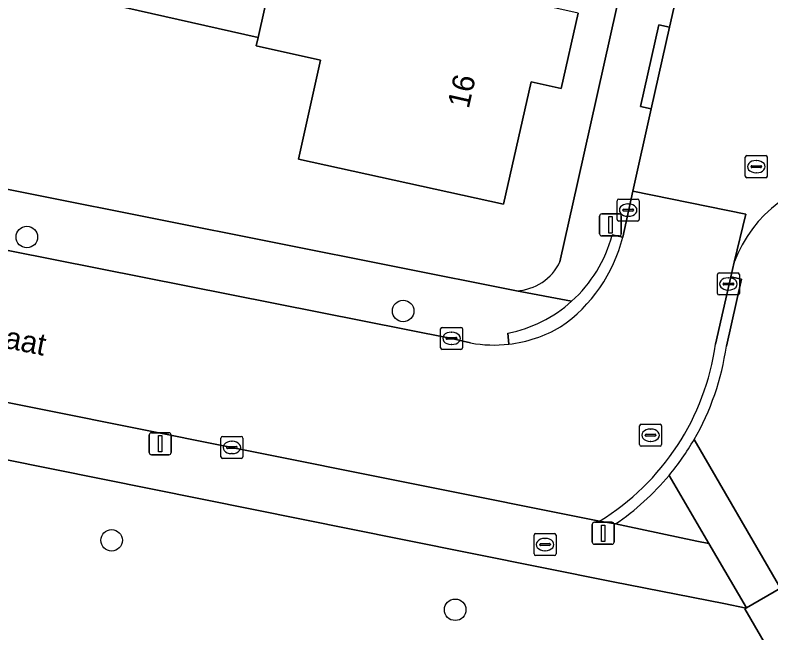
# Model space of a CAD drawing. Extents: x 161771 to 163125, y 382475 to 383179.
# Drawn here: x 162596.63 to 162630.99, y 382576.02 to 382604.09 of the extents above; entities that cross this region are included whole.
import ezdxf

# ---------------------------------------------------------------- set-up
doc = ezdxf.new("R2010")
doc.units = 0
for name, color, linetype in [('IMGEO_Boom', 7, 'Continuous'), ('IMGEO_Brandkraan', 7, 'Continuous'), ('IMGEO_Erf', 7, 'Continuous'), ('IMGEO_Groenvoorziening', 7, 'Continuous'), ('IMGEO_Kolk', 7, 'Continuous'), ('IMGEO_Lichtmast', 7, 'Continuous'), ('IMGEO_Openbare_ruimte_label', 7, 'Continuous'), ('IMGEO_Pand', 7, 'Continuous'), ('IMGEO_Pand_nummerreeks', 7, 'Continuous'), ('IMGEO_Rijbaan_lokaal_open', 7, 'Continuous'), ('IMGEO_Rioolput', 7, 'Continuous'), ('IMGEO_Voetpad_gesloten', 7, 'Continuous'), ('IMGEO_Voetpad_open', 7, 'Continuous')]:
    doc.layers.add(name, color=color, linetype=linetype)

msp = doc.modelspace()

# ---------------------------------------------------------------- linework, layer by layer
at = {"layer": 'IMGEO_Boom'}
for centre in [(162597.163, 382594.003), (162614.272, 382590.645), (162601.016, 382580.221), (162616.637, 382577.065)]:
    msp.add_circle(centre, 0.489, dxfattribs=at)
at = {"layer": 'IMGEO_Brandkraan'}
for p, q in [((162620.221, 382579.603), (162620.221, 382580.455)), ((162620.296, 382580.529), (162621.148, 382580.529)), ((162620.709, 382580.309), (162620.734, 382580.309)), ((162621.222, 382580.455), (162621.222, 382579.603)), ((162620.48, 382580.023), (162620.48, 382580.035)), ((162620.918, 382579.986), (162620.52, 382579.986)), ((162620.523, 382580.072), (162620.921, 382580.072)), ((162620.964, 382580.035), (162620.964, 382580.023)), ((162620.732, 382579.749), (162620.707, 382579.749)), ((162621.148, 382579.529), (162620.296, 382579.529))]:
    msp.add_line(p, q, dxfattribs=at)
for points in [[(162620.221, 382579.603), (162620.221, 382580.455)], [(162620.296, 382580.529), (162621.148, 382580.529)], [(162621.222, 382580.455), (162621.222, 382579.603)], [(162621.148, 382579.529), (162620.296, 382579.529)]]:
    msp.add_lwpolyline(points, dxfattribs=at)
for centre, radius, start, end in [((162620.298, 382580.453), 0.0765, 91.552, 178.448), ((162620.298, 382580.453), 0.0765, 91.552, 178.448), ((162621.146, 382580.453), 0.0765, 1.552, 88.448), ((162621.146, 382580.453), 0.0765, 1.552, 88.448), ((162620.52, 382580.032), 0.0403, 85.8775, 175.7526), ((162620.517, 382580.022), 0.0366, 178.938, 274.7102), ((162620.921, 382580.029), 0.043, 264.8664, 352.4533), ((162620.925, 382580.034), 0.0386, 1.7309, 96.639), ((162620.298, 382579.605), 0.0765, 181.552, 268.448), ((162620.298, 382579.605), 0.0765, 181.552, 268.448), ((162621.146, 382579.605), 0.0765, 271.552, 358.448), ((162621.146, 382579.605), 0.0765, 271.552, 358.448)]:
    msp.add_arc(centre, radius, start, end, dxfattribs=at)
for centre, major_axis, ratio, start_param, end_param in [((162620.708, 382580.029), (-0.387, 0.002), 0.722429, 4.712389, 7.853982), ((162620.733, 382580.029), (-0.39, 0.002), 0.717154, 1.570796, 4.712389)]:
    msp.add_ellipse(centre, major_axis=major_axis, ratio=ratio, start_param=start_param, end_param=end_param, dxfattribs=at)
at = {"layer": 'IMGEO_Erf'}
for points in [[(162621.402, 382592.881), (162622.207, 382596.532), (162640.083, 382676.445)], [(162622.231, 382604.183), (162621.454, 382600.75), (162620.096, 382601.054), (162618.835, 382595.504), (162609.511, 382597.549), (162610.517, 382602.039), (162607.589, 382602.695), (162607.674, 382603.072), (162601.611, 382604.432)], [(162574.205, 382600.57), (162575.646, 382600.287), (162619.42, 382591.558)]]:
    msp.add_lwpolyline(points, dxfattribs=at)
msp.add_arc((162619.308, 382593.872), 2.317, 272.7701, 334.6767, dxfattribs=at)
at = {"layer": 'IMGEO_Groenvoorziening'}
for points in [[(162629.327, 382592.855), (162629.169, 382592.195), (162629.658, 382592.087), (162628.966, 382589.047)], [(162627.498, 382584.799), (162631.342, 382578.199)], [(162637.821, 382563.285), (162629.801, 382577.101), (162629.868, 382577.139), (162628.853, 382577.346), (162623.821, 382578.342), (162614.239, 382580.265), (162596.033, 382583.918), (162595.635, 382582.109)], [(162623.928, 382580.964), (162624.356, 382580.88), (162627.617, 382580.186), (162628.173, 382580.075), (162626.361, 382583.171)]]:
    msp.add_lwpolyline(points, dxfattribs=at)
for centre, radius, start, end in [((162634.942, 382590.791), 5.982, 94.064, 159.8134), ((162617.334, 382590.689), 11.748, 329.9078, 351.9645), ((162617.33, 382590.682), 11.746, 304.1735, 320.2495)]:
    msp.add_arc(centre, radius, start, end, dxfattribs=at)
at = {"layer": 'IMGEO_Kolk'}
for p, q in [((162629.828, 382596.776), (162629.828, 382597.628)), ((162629.903, 382597.702), (162630.755, 382597.702)), ((162630.316, 382597.482), (162630.341, 382597.482)), ((162630.829, 382597.628), (162630.829, 382596.776)), ((162630.087, 382597.196), (162630.087, 382597.208)), ((162630.525, 382597.159), (162630.127, 382597.159)), ((162630.13, 382597.245), (162630.528, 382597.245)), ((162630.571, 382597.208), (162630.571, 382597.196)), ((162630.339, 382596.922), (162630.314, 382596.922)), ((162630.755, 382596.702), (162629.903, 382596.702)), ((162624.001, 382594.803), (162624.001, 382595.655)), ((162624.076, 382595.729), (162624.928, 382595.729)), ((162624.489, 382595.509), (162624.514, 382595.509)), ((162625.002, 382595.655), (162625.002, 382594.803)), ((162624.26, 382595.223), (162624.26, 382595.235)), ((162624.698, 382595.186), (162624.3, 382595.186)), ((162624.303, 382595.272), (162624.701, 382595.272)), ((162624.744, 382595.235), (162624.744, 382595.223)), ((162624.928, 382594.729), (162624.076, 382594.729)), ((162624.512, 382594.949), (162624.487, 382594.949)), ((162628.632, 382592.371), (162629.484, 382592.371)), ((162628.557, 382591.445), (162628.557, 382592.297)), ((162629.045, 382592.151), (162629.07, 382592.151)), ((162629.558, 382592.297), (162629.558, 382591.445)), ((162628.816, 382591.865), (162628.816, 382591.877)), ((162629.254, 382591.828), (162628.856, 382591.828)), ((162628.859, 382591.914), (162629.257, 382591.914)), ((162629.3, 382591.877), (162629.3, 382591.865)), ((162629.484, 382591.371), (162628.632, 382591.371)), ((162629.068, 382591.591), (162629.043, 382591.591)), ((162615.971, 382588.974), (162615.971, 382589.826)), ((162616.046, 382589.9), (162616.898, 382589.9)), ((162616.459, 382589.68), (162616.484, 382589.68)), ((162616.972, 382589.826), (162616.972, 382588.974)), ((162616.23, 382589.394), (162616.23, 382589.406)), ((162616.668, 382589.357), (162616.27, 382589.357)), ((162616.273, 382589.443), (162616.671, 382589.443)), ((162616.714, 382589.406), (162616.714, 382589.394)), ((162616.898, 382588.9), (162616.046, 382588.9)), ((162616.482, 382589.12), (162616.457, 382589.12)), ((162605.984, 382584.015), (162605.984, 382584.867)), ((162606.059, 382584.941), (162606.911, 382584.941)), ((162606.985, 382584.867), (162606.985, 382584.015)), ((162606.243, 382584.435), (162606.243, 382584.447)), ((162606.286, 382584.484), (162606.684, 382584.484)), ((162606.472, 382584.721), (162606.497, 382584.721)), ((162606.727, 382584.447), (162606.727, 382584.435)), ((162606.681, 382584.398), (162606.283, 382584.398)), ((162606.495, 382584.161), (162606.47, 382584.161)), ((162606.911, 382583.941), (162606.059, 382583.941))]:
    msp.add_line(p, q, dxfattribs=at)
for points in [[(162629.828, 382596.776), (162629.828, 382597.628)], [(162629.903, 382597.702), (162630.755, 382597.702)], [(162630.829, 382597.628), (162630.829, 382596.776)], [(162630.755, 382596.702), (162629.903, 382596.702)], [(162624.001, 382594.803), (162624.001, 382595.655)], [(162624.076, 382595.729), (162624.928, 382595.729)], [(162625.002, 382595.655), (162625.002, 382594.803)], [(162624.928, 382594.729), (162624.076, 382594.729)], [(162628.632, 382592.371), (162629.484, 382592.371)], [(162628.557, 382591.445), (162628.557, 382592.297)], [(162629.558, 382592.297), (162629.558, 382591.445)], [(162629.484, 382591.371), (162628.632, 382591.371)], [(162615.971, 382588.974), (162615.971, 382589.826)], [(162616.046, 382589.9), (162616.898, 382589.9)], [(162616.972, 382589.826), (162616.972, 382588.974)], [(162616.898, 382588.9), (162616.046, 382588.9)], [(162605.984, 382584.015), (162605.984, 382584.867)], [(162606.059, 382584.941), (162606.911, 382584.941)], [(162606.985, 382584.867), (162606.985, 382584.015)], [(162606.911, 382583.941), (162606.059, 382583.941)]]:
    msp.add_lwpolyline(points, dxfattribs=at)
for centre, radius, start, end in [((162629.905, 382597.626), 0.0765, 91.552, 178.448), ((162629.905, 382597.626), 0.0765, 91.552, 178.448), ((162630.753, 382597.626), 0.0765, 1.552, 88.448), ((162630.753, 382597.626), 0.0765, 1.552, 88.448), ((162630.127, 382597.205), 0.0403, 85.8775, 175.7526), ((162630.124, 382597.195), 0.0366, 178.938, 274.7102), ((162630.528, 382597.202), 0.043, 264.8664, 352.4533), ((162630.532, 382597.207), 0.0386, 1.7309, 96.639), ((162629.905, 382596.778), 0.0765, 181.552, 268.448), ((162629.905, 382596.778), 0.0765, 181.552, 268.448), ((162630.753, 382596.778), 0.0765, 271.552, 358.448), ((162630.753, 382596.778), 0.0765, 271.552, 358.448), ((162624.078, 382595.653), 0.0765, 91.552, 178.448), ((162624.078, 382595.653), 0.0765, 91.552, 178.448), ((162624.926, 382595.653), 0.0765, 1.552, 88.448), ((162624.926, 382595.653), 0.0765, 1.552, 88.448), ((162624.3, 382595.232), 0.0403, 85.8775, 175.7526), ((162624.297, 382595.222), 0.0366, 178.938, 274.7102), ((162624.701, 382595.229), 0.043, 264.8664, 352.4533), ((162624.705, 382595.234), 0.0386, 1.7309, 96.639), ((162624.078, 382594.805), 0.0765, 181.552, 268.448), ((162624.078, 382594.805), 0.0765, 181.552, 268.448), ((162624.926, 382594.805), 0.0765, 271.552, 358.448), ((162624.926, 382594.805), 0.0765, 271.552, 358.448), ((162628.634, 382592.295), 0.0765, 91.552, 178.448), ((162628.634, 382592.295), 0.0765, 91.552, 178.448), ((162629.482, 382592.295), 0.0765, 1.552, 88.448), ((162629.482, 382592.295), 0.0765, 1.552, 88.448), ((162628.856, 382591.874), 0.0403, 85.8775, 175.7526), ((162628.853, 382591.864), 0.0366, 178.938, 274.7102), ((162629.257, 382591.871), 0.043, 264.8664, 352.4533), ((162629.261, 382591.876), 0.0386, 1.7309, 96.639), ((162628.634, 382591.447), 0.0765, 181.552, 268.448), ((162628.634, 382591.447), 0.0765, 181.552, 268.448), ((162629.482, 382591.447), 0.0765, 271.552, 358.448), ((162629.482, 382591.447), 0.0765, 271.552, 358.448), ((162616.048, 382589.824), 0.0765, 91.552, 178.448), ((162616.048, 382589.824), 0.0765, 91.552, 178.448), ((162616.896, 382589.824), 0.0765, 1.552, 88.448), ((162616.896, 382589.824), 0.0765, 1.552, 88.448), ((162616.27, 382589.403), 0.0403, 85.8775, 175.7526), ((162616.267, 382589.393), 0.0366, 178.938, 274.7102), ((162616.671, 382589.4), 0.043, 264.8664, 352.4533), ((162616.675, 382589.405), 0.0386, 1.7309, 96.639), ((162616.048, 382588.976), 0.0765, 181.552, 268.448), ((162616.048, 382588.976), 0.0765, 181.552, 268.448), ((162616.896, 382588.976), 0.0765, 271.552, 358.448), ((162616.896, 382588.976), 0.0765, 271.552, 358.448), ((162606.061, 382584.865), 0.0765, 91.552, 178.448), ((162606.061, 382584.865), 0.0765, 91.552, 178.448), ((162606.909, 382584.865), 0.0765, 1.552, 88.448), ((162606.909, 382584.865), 0.0765, 1.552, 88.448), ((162606.283, 382584.444), 0.0403, 85.8775, 175.7526), ((162606.28, 382584.434), 0.0366, 178.938, 274.7102), ((162606.684, 382584.441), 0.043, 264.8664, 352.4533), ((162606.688, 382584.446), 0.0386, 1.7309, 96.639), ((162606.061, 382584.017), 0.0765, 181.552, 268.448), ((162606.061, 382584.017), 0.0765, 181.552, 268.448), ((162606.909, 382584.017), 0.0765, 271.552, 358.448), ((162606.909, 382584.017), 0.0765, 271.552, 358.448)]:
    msp.add_arc(centre, radius, start, end, dxfattribs=at)
for centre, major_axis, ratio, start_param, end_param in [((162630.315, 382597.202), (-0.387, 0.002), 0.722429, 4.712389, 7.853982), ((162630.34, 382597.202), (-0.39, 0.002), 0.717154, 1.570796, 4.712389), ((162624.488, 382595.229), (-0.387, 0.002), 0.722429, 4.712389, 7.853982), ((162624.513, 382595.229), (-0.39, 0.002), 0.717154, 1.570796, 4.712389), ((162629.044, 382591.871), (-0.387, 0.002), 0.722429, 4.712389, 7.853982), ((162629.069, 382591.871), (-0.39, 0.002), 0.717154, 1.570796, 4.712389), ((162616.458, 382589.4), (-0.387, 0.002), 0.722429, 4.712389, 7.853982), ((162616.483, 382589.4), (-0.39, 0.002), 0.717154, 1.570796, 4.712389), ((162606.471, 382584.441), (-0.387, 0.002), 0.722429, 4.712389, 7.853982), ((162606.496, 382584.441), (-0.39, 0.002), 0.717154, 1.570796, 4.712389)]:
    msp.add_ellipse(centre, major_axis=major_axis, ratio=ratio, start_param=start_param, end_param=end_param, dxfattribs=at)
at = {"layer": 'IMGEO_Lichtmast'}
for p, q in [((162623.201, 382594.156), (162623.201, 382594.956)), ((162623.201, 382594.956), (162623.201, 382594.156)), ((162623.301, 382595.056), (162624.091, 382595.056)), ((162624.091, 382595.056), (162623.301, 382595.056)), ((162624.191, 382594.956), (162624.191, 382594.156)), ((162624.191, 382594.156), (162624.191, 382594.956)), ((162624.091, 382594.056), (162623.301, 382594.056)), ((162623.301, 382594.056), (162624.091, 382594.056)), ((162602.831, 382585.111), (162603.621, 382585.111)), ((162603.621, 382585.111), (162602.831, 382585.111)), ((162602.731, 382584.211), (162602.731, 382585.011)), ((162602.731, 382585.011), (162602.731, 382584.211)), ((162603.721, 382585.011), (162603.721, 382584.211)), ((162603.721, 382584.211), (162603.721, 382585.011)), ((162603.621, 382584.111), (162602.831, 382584.111)), ((162602.831, 382584.111), (162603.621, 382584.111)), ((162622.972, 382581.041), (162623.762, 382581.041)), ((162623.762, 382581.041), (162622.972, 382581.041)), ((162622.872, 382580.141), (162622.872, 382580.941)), ((162622.872, 382580.941), (162622.872, 382580.141)), ((162623.862, 382580.941), (162623.862, 382580.141)), ((162623.862, 382580.141), (162623.862, 382580.941)), ((162623.762, 382580.041), (162622.972, 382580.041)), ((162622.972, 382580.041), (162623.762, 382580.041))]:
    msp.add_line(p, q, dxfattribs=at)
for points in [[(162623.621, 382594.931), (162623.771, 382594.931), (162623.771, 382594.181), (162623.621, 382594.181), (162623.621, 382594.931)], [(162603.151, 382584.986), (162603.301, 382584.986), (162603.301, 382584.236), (162603.151, 382584.236), (162603.151, 382584.986)], [(162623.292, 382580.916), (162623.442, 382580.916), (162623.442, 382580.166), (162623.292, 382580.166), (162623.292, 382580.916)]]:
    msp.add_lwpolyline(points, dxfattribs=at)
for centre, start, end in [((162623.301, 382594.956), 90, 180), ((162623.301, 382594.956), 90, 180), ((162624.091, 382594.956), 0, 90), ((162624.091, 382594.956), 360, 90), ((162623.301, 382594.156), 180, 270), ((162623.301, 382594.156), 180, 270), ((162624.091, 382594.156), 270, 0), ((162624.091, 382594.156), 270, 0), ((162602.831, 382585.011), 90, 180), ((162602.831, 382585.011), 90, 180), ((162603.621, 382585.011), 0, 90), ((162603.621, 382585.011), 360, 90), ((162602.831, 382584.211), 180, 270), ((162602.831, 382584.211), 180, 270), ((162603.621, 382584.211), 270, 0), ((162603.621, 382584.211), 270, 0), ((162622.972, 382580.941), 90, 180), ((162622.972, 382580.941), 90, 180), ((162623.762, 382580.941), 0, 90), ((162623.762, 382580.941), 360, 90), ((162622.972, 382580.141), 180, 270), ((162622.972, 382580.141), 180, 270), ((162623.762, 382580.141), 270, 0), ((162623.762, 382580.141), 270, 0)]:
    msp.add_arc(centre, 0.1, start, end, dxfattribs=at)
at = {"layer": 'IMGEO_Pand'}
for points in [[(162608.603, 382607.222), (162602.54, 382608.574), (162602.596, 382608.823), (162600.4, 382609.315), (162599.415, 382604.924), (162601.611, 382604.432), (162607.674, 382603.072)], [(162622.231, 382604.183), (162608.603, 382607.222), (162607.674, 382603.072), (162607.589, 382602.695), (162610.517, 382602.039), (162609.511, 382597.549), (162618.835, 382595.504), (162620.096, 382601.054), (162621.454, 382600.75)]]:
    msp.add_lwpolyline(points, close=True, dxfattribs=at)
at = {"layer": 'IMGEO_Rijbaan_lokaal_open'}
for points in [[(162631.396, 382626.021), (162630.297, 382621.123), (162629.498, 382617.399), (162628.987, 382615.158), (162628.293, 382612.132), (162627.486, 382608.423), (162626.379, 382603.537), (162625.55, 382599.824), (162624.721, 382596.089), (162629.852, 382595.048), (162629.327, 382592.855)], [(162553.952, 382601.516), (162547.986, 382603.221), (162545.474, 382603.995), (162543.524, 382597.351), (162543.945, 382597.266), (162545.895, 382596.834), (162551.536, 382595.604), (162557.902, 382594.164), (162567.186, 382592.352), (162568.262, 382592.109), (162606.49, 382584.441), (162623.202, 382581.091)], [(162628.475, 382589.143), (162629.169, 382592.195), (162629.327, 382592.855), (162629.852, 382595.048), (162624.721, 382596.089), (162624.258, 382594)], [(162617.34, 382589.193), (162616.468, 382589.4), (162592.4, 382594.172)]]:
    msp.add_lwpolyline(points, dxfattribs=at)
for centre, radius, start, end in [((162634.942, 382590.791), 5.982, 94.064, 159.8134), ((162617.457, 382595.697), 7.009, 304.4978, 345.9907), ((162618.404, 382595.059), 5.962, 276.4786, 300.4644), ((162618.404, 382595.024), 5.927, 259.6569, 276.5182), ((162617.298, 382590.71), 11.287, 301.5421, 352.0189)]:
    msp.add_arc(centre, radius, start, end, dxfattribs=at)
at = {"layer": 'IMGEO_Rioolput'}
for p, q in [((162625.098, 382585.497), (162625.95, 382585.497)), ((162625.023, 382584.571), (162625.023, 382585.423)), ((162625.511, 382585.277), (162625.536, 382585.277)), ((162626.024, 382585.423), (162626.024, 382584.571)), ((162625.282, 382584.991), (162625.282, 382585.003)), ((162625.72, 382584.954), (162625.322, 382584.954)), ((162625.325, 382585.04), (162625.723, 382585.04)), ((162625.766, 382585.003), (162625.766, 382584.991)), ((162625.95, 382584.497), (162625.098, 382584.497)), ((162625.534, 382584.717), (162625.509, 382584.717))]:
    msp.add_line(p, q, dxfattribs=at)
for points in [[(162625.098, 382585.497), (162625.95, 382585.497)], [(162625.023, 382584.571), (162625.023, 382585.423)], [(162626.024, 382585.423), (162626.024, 382584.571)], [(162625.95, 382584.497), (162625.098, 382584.497)]]:
    msp.add_lwpolyline(points, dxfattribs=at)
for centre, radius, start, end in [((162625.1, 382585.421), 0.0765, 91.552, 178.448), ((162625.1, 382585.421), 0.0765, 91.552, 178.448), ((162625.948, 382585.421), 0.0765, 1.552, 88.448), ((162625.948, 382585.421), 0.0765, 1.552, 88.448), ((162625.322, 382585), 0.0403, 85.8775, 175.7526), ((162625.319, 382584.99), 0.0366, 178.938, 274.7102), ((162625.723, 382584.997), 0.043, 264.8664, 352.4533), ((162625.727, 382585.002), 0.0386, 1.7309, 96.639), ((162625.1, 382584.573), 0.0765, 181.552, 268.448), ((162625.1, 382584.573), 0.0765, 181.552, 268.448), ((162625.948, 382584.573), 0.0765, 271.552, 358.448), ((162625.948, 382584.573), 0.0765, 271.552, 358.448)]:
    msp.add_arc(centre, radius, start, end, dxfattribs=at)
for centre, major_axis, ratio, start_param, end_param in [((162625.51, 382584.997), (-0.387, 0.002), 0.722429, 4.712389, 7.853982), ((162625.535, 382584.997), (-0.39, 0.002), 0.717154, 1.570796, 4.712389)]:
    msp.add_ellipse(centre, major_axis=major_axis, ratio=ratio, start_param=start_param, end_param=end_param, dxfattribs=at)
at = {"layer": 'IMGEO_Voetpad_gesloten'}
msp.add_lwpolyline([(162632.375, 382576.584), (162631.505, 382578.083), (162631.434, 382578.042), (162629.886, 382577.15), (162629.868, 382577.139), (162629.801, 382577.101), (162637.821, 382563.285), (162639.517, 382564.278)], close=True, dxfattribs=at)
at = {"layer": 'IMGEO_Voetpad_open'}
for points in [[(162643.112, 382689.963), (162641.523, 382682.919), (162640.083, 382676.445), (162622.207, 382596.532), (162621.402, 382592.881)], [(162623.768, 382594.099), (162624.258, 382594), (162624.721, 382596.089), (162625.55, 382599.824), (162625.063, 382599.932), (162625.892, 382603.645), (162626.379, 382603.537), (162627.486, 382608.423), (162626.998, 382608.529), (162627.805, 382612.238), (162628.293, 382612.132), (162628.987, 382615.158), (162629.498, 382617.399), (162629.01, 382617.503), (162629.809, 382621.227), (162630.297, 382621.123), (162631.396, 382626.021)], [(162621.933, 382591.086), (162619.42, 382591.558), (162575.646, 382600.287)], [(162574.261, 382597.773), (162592.4, 382594.172), (162616.468, 382589.4), (162617.34, 382589.193)], [(162532.214, 382594.288), (162536.955, 382592.903), (162539.493, 382592.162), (162544.465, 382590.71), (162546.975, 382589.993), (162570.463, 382583.09), (162572.485, 382586.757), (162573.64, 382588.411), (162582.199, 382586.694), (162594.168, 382584.292), (162596.033, 382583.918), (162614.239, 382580.265), (162623.821, 382578.342), (162628.853, 382577.346), (162629.868, 382577.139), (162629.886, 382577.15), (162628.173, 382580.075), (162627.617, 382580.186), (162624.356, 382580.88), (162623.928, 382580.964), (162623.202, 382581.091), (162606.49, 382584.441), (162568.262, 382592.109)], [(162624.258, 382594), (162623.768, 382594.099)], [(162629.658, 382592.087), (162629.169, 382592.195), (162628.475, 382589.143)], [(162628.966, 382589.047), (162629.658, 382592.087)], [(162619.42, 382591.558), (162621.933, 382591.086)], [(162619.077, 382589.135), (162619.035, 382589.634)], [(162619.035, 382589.634), (162619.077, 382589.135)], [(162626.361, 382583.171), (162628.173, 382580.075), (162629.886, 382577.15), (162631.434, 382578.042), (162631.342, 382578.199), (162627.498, 382584.799)], [(162623.202, 382581.091), (162623.928, 382580.964)]]:
    msp.add_lwpolyline(points, dxfattribs=at)
msp.add_lwpolyline([(162625.55, 382599.824), (162626.379, 382603.537), (162625.892, 382603.645), (162625.063, 382599.932)], close=True, dxfattribs=at)
for centre, radius, start, end in [((162617.861, 382595.631), 6.102, 311.8565, 345.4584), ((162617.861, 382595.631), 6.102, 311.8565, 345.4584), ((162617.457, 382595.697), 7.009, 304.4978, 345.9907), ((162619.308, 382593.872), 2.317, 272.7701, 334.6767), ((162617.837, 382595.643), 6.127, 281.2741, 311.9509), ((162617.837, 382595.643), 6.127, 281.2741, 311.9509), ((162618.404, 382595.059), 5.962, 276.4786, 300.4644), ((162618.404, 382595.024), 5.927, 259.6569, 276.5182), ((162617.298, 382590.71), 11.287, 301.5421, 352.0189), ((162617.334, 382590.689), 11.748, 329.9078, 351.9645), ((162617.319, 382590.697), 11.764, 320.2279, 329.9109), ((162617.319, 382590.697), 11.764, 320.2279, 329.9109), ((162617.33, 382590.682), 11.746, 304.1735, 320.2495)]:
    msp.add_arc(centre, radius, start, end, dxfattribs=at)

# ---------------------------------------------------------------- texts
at = {"layer": 'IMGEO_Openbare_ruimte_label'}
msp.add_text('van Wassenhovestraat', height=1, rotation=348.6339, dxfattribs=at).set_placement((162584.583, 382591.29))
at = {"layer": 'IMGEO_Pand_nummerreeks'}
msp.add_text('16', height=1, rotation=77.3608, dxfattribs=at).set_placement((162617.25, 382599.803))

doc.saveas('drawing.dxf')
